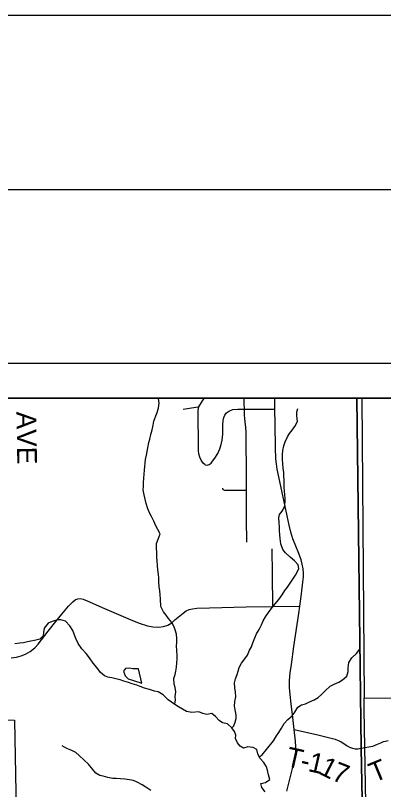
# Model space of a CAD drawing. Extents: x 0 to 34, y 0 to 22.
# Drawn here: x 5.25 to 6.308, y 19.775 to 22 of the extents above; entities that cross this region are included whole.
import ezdxf

# ---------------------------------------------------------------- set-up
doc = ezdxf.new("R2010")
doc.units = 0
for name, color, linetype in [('Default', 7, 'Continuous'), ('SH_Border', 7, 'Continuous'), ('SH_Cut_Line', 7, 'Continuous'), ('SH_Data', 7, 'Continuous')]:
    doc.layers.add(name, color=color, linetype=linetype)

msp = doc.modelspace()

# ---------------------------------------------------------------- linework, layer by layer
at = {"layer": 'Default'}
for points in [[(6.2766, 18.3021), (6.2705, 18.5012), (6.2432, 19.8937), (6.2315, 20.9), (2.1, 20.9)], [(5.7078, 20.0197), (5.7099, 20.0328), (5.709, 20.0422), (5.7106, 20.0559), (5.7089, 20.0677), (5.7056, 20.0775), (5.7049, 20.0935), (5.7085, 20.1057), (5.711, 20.1152), (5.7131, 20.1259), (5.714, 20.1388), (5.7145, 20.1499), (5.7143, 20.1594), (5.7136, 20.1742), (5.713, 20.1875), (5.714, 20.197), (5.7141, 20.2088), (5.7127, 20.2213), (5.7091, 20.2341), (5.7051, 20.2447), (5.6992, 20.2548), (5.6894, 20.2664), (5.6828, 20.2762), (5.675, 20.2859), (5.6678, 20.301), (5.6666, 20.323), (5.6653, 20.3344), (5.6643, 20.3472), (5.6633, 20.3567), (5.6623, 20.3723), (5.6617, 20.3833), (5.6607, 20.3928), (5.6593, 20.4061), (5.658, 20.4186), (5.6569, 20.4322), (5.6563, 20.4429), (5.6556, 20.4816), (5.6603, 20.4946), (5.6657, 20.5099), (5.659, 20.5223), (5.6535, 20.5329), (5.6479, 20.5464), (5.6404, 20.5596), (5.6349, 20.5701), (5.6305, 20.5818), (5.6256, 20.5969), (5.6223, 20.6098), (5.6194, 20.6222), (5.6172, 20.6359), (5.6174, 20.6458), (5.6176, 20.6564), (5.6185, 20.6693), (5.6198, 20.6815), (5.6211, 20.6926), (5.622, 20.7029), (5.6226, 20.7124), (5.6239, 20.7234), (5.626, 20.7356), (5.628, 20.7463), (5.6301, 20.7574), (5.6336, 20.7719), (5.6365, 20.7818), (5.6393, 20.7955), (5.6424, 20.8089), (5.6452, 20.8222), (5.6477, 20.8337), (5.6535, 20.8486), (5.6571, 20.8582), (5.6614, 20.872), (5.6626, 20.8853), (5.6609, 20.8986), (5.66, 20.9)], [(5.7765, 20.8745), (5.7871, 20.892), (5.7932, 20.9)], [(5.9148, 20.4853), (5.9135, 20.5521), (5.9139, 20.6343), (5.9135, 20.6961), (5.9132, 20.7724), (5.9125, 20.8022), (5.9117, 20.8165), (5.9102, 20.8305), (5.9078, 20.8516), (5.9078, 20.8677), (5.907, 20.8853), (5.9071, 20.9)], [(6.0294, 19.7703), (6.043, 19.8235), (6.0507, 19.8542), (6.054, 19.8702), (6.0556, 19.8831), (6.0558, 19.8974), (6.0547, 19.9136), (6.0509, 19.9471), (6.0469, 19.9819), (6.0423, 20.0205), (6.0395, 20.0481), (6.0379, 20.0678), (6.0379, 20.0885), (6.0396, 20.1096), (6.0429, 20.1342), (6.0503, 20.1859), (6.0643, 20.2808), (6.0674, 20.3022), (6.071, 20.3296), (6.076, 20.3703), (6.0775, 20.3858), (6.0776, 20.3968), (6.0768, 20.4092), (6.0744, 20.4225), (6.0708, 20.4354), (6.0645, 20.4529), (6.0554, 20.4745), (6.0472, 20.4956), (6.0415, 20.5146), (6.0368, 20.5342), (6.031, 20.5616), (6.0128, 20.6469), (6.0025, 20.6954), (5.9999, 20.7106), (5.9982, 20.7256), (5.997, 20.7568), (5.9963, 20.8247), (5.9958, 20.8681), (5.9956, 20.8961), (5.9956, 20.9)], [(8.9, 20.9), (6.2315, 20.9), (6.2432, 19.8937), (6.2705, 18.5012), (6.2766, 18.3021), (6.2818, 17.7893), (6.284, 17.7847), (6.2852, 17.7812), (6.2857, 17.7766), (6.2851, 17.77), (6.2847, 17.7673), (6.2837, 17.7609), (6.2829, 17.749), (6.2828, 17.7387), (6.2833, 17.73), (6.2837, 17.7277), (6.2841, 17.7253), (6.2843, 17.721), (6.2843, 17.7119), (6.2861, 17.2714), (6.2871, 17.0188), (6.3215, 17.0189)], [(5.7317, 20.8678), (5.7678, 20.8734), (5.7765, 20.8745)], [(5.7953, 20.7084), (5.7897, 20.7131), (5.784, 20.7212), (5.7801, 20.7298), (5.7773, 20.7394), (5.7762, 20.7495), (5.7758, 20.7573), (5.7755, 20.791), (5.775, 20.8268), (5.7751, 20.8501), (5.7751, 20.8641), (5.7765, 20.8745)], [(5.7953, 20.7084), (5.8007, 20.7072), (5.807, 20.7092), (5.8122, 20.7133), (5.8166, 20.7186), (5.8231, 20.7273), (5.8314, 20.7405), (5.8372, 20.7537), (5.8414, 20.7669), (5.8442, 20.7794), (5.8456, 20.7961), (5.846, 20.8233), (5.8467, 20.8352), (5.8488, 20.8441), (5.852, 20.8509), (5.8569, 20.8577), (5.8646, 20.8632), (5.8748, 20.8667), (5.8887, 20.8678), (5.9078, 20.8677), (5.9536, 20.8678), (5.9958, 20.8681)], [(5.8715, 19.9519), (5.8776, 19.9581), (5.8812, 19.9681), (5.8841, 19.9792), (5.8842, 19.9887), (5.8825, 19.9989), (5.8792, 20.0144), (5.8805, 20.0273), (5.8829, 20.0407), (5.8826, 20.0544), (5.8801, 20.0672), (5.879, 20.0813), (5.8819, 20.0927), (5.8869, 20.1057), (5.8898, 20.1153), (5.893, 20.1256), (5.9, 20.1379), (5.9093, 20.1499), (5.9167, 20.161), (5.9229, 20.1748), (5.928, 20.1844), (5.9324, 20.1967), (5.9382, 20.2105), (5.9429, 20.2224), (5.9499, 20.2343), (5.9569, 20.2477), (5.962, 20.2596), (5.9686, 20.2707), (5.9767, 20.2834), (5.9875, 20.2981), (5.996, 20.3085), (6.0064, 20.3212), (6.0161, 20.334), (6.0246, 20.3467), (6.032, 20.3567), (6.039, 20.3679), (6.0471, 20.3798), (6.0545, 20.391), (6.0601, 20.401), (6.0641, 20.4105), (6.062, 20.4204), (6.0518, 20.432), (6.0398, 20.4427), (6.0263, 20.455), (6.0181, 20.4651), (6.0128, 20.4813), (6.011, 20.4961), (6.0101, 20.5064), (6.0091, 20.5181), (6.0085, 20.5295), (6.0075, 20.5409), (6.0065, 20.5557), (6.0086, 20.5652), (6.0167, 20.5749), (6.023, 20.586), (6.0254, 20.6013), (6.0252, 20.6119), (6.0242, 20.6214), (6.0228, 20.6335), (6.0223, 20.643), (6.0221, 20.6537), (6.0223, 20.6639), (6.0216, 20.6761), (6.0211, 20.6856), (6.0193, 20.6988), (6.0187, 20.7114), (6.0173, 20.7246), (6.017, 20.7379), (6.0183, 20.7494), (6.0211, 20.7627), (6.0247, 20.7738), (6.0317, 20.7884), (6.0379, 20.7984), (6.045, 20.808), (6.0546, 20.8211), (6.0601, 20.8341), (6.0583, 20.8482), (6.0588, 20.8607), (6.0616, 20.8703)], [(5.9139, 20.6343), (5.8515, 20.6339), (5.8473, 20.6364), (5.8455, 20.6409)], [(5.9895, 20.3009), (5.9882, 20.3934), (5.9873, 20.467)], [(5.2378, 20.1528), (5.2524, 20.1548), (5.2659, 20.1586), (5.2786, 20.1637), (5.2919, 20.171), (5.3055, 20.1818), (5.3152, 20.1928), (5.3439, 20.2295), (5.3657, 20.2572), (5.3834, 20.279), (5.4021, 20.3014), (5.4144, 20.3141), (5.4226, 20.3205), (5.4292, 20.3232), (5.4359, 20.3239), (5.4439, 20.322), (5.4556, 20.317), (5.5056, 20.2948), (5.5797, 20.2633), (5.6054, 20.2528), (5.6291, 20.2456), (5.6444, 20.2421), (5.6607, 20.2413), (5.6749, 20.2428), (5.6877, 20.247), (5.6988, 20.2538), (5.7082, 20.2621), (5.7315, 20.2819), (5.7404, 20.2881), (5.7489, 20.2922), (5.759, 20.2945), (5.7713, 20.2957), (5.8078, 20.2968), (5.9133, 20.2994), (5.9895, 20.3009), (6.0674, 20.3022)], [(5.9676, 19.7676), (5.9583, 19.7803), (5.9554, 19.7917), (5.9683, 19.7946), (5.9807, 19.8032), (5.977, 19.8168), (5.9741, 19.8301), (5.9712, 19.8399), (5.9637, 19.8523), (5.9525, 19.865), (5.9461, 19.877), (5.9436, 19.8895), (5.9328, 19.8954), (5.918, 19.8977), (5.9055, 19.8937), (5.8959, 19.8988), (5.8885, 19.9086), (5.8821, 19.9214), (5.8831, 19.9313), (5.8798, 19.9411), (5.8713, 19.9523), (5.8589, 19.9635), (5.8451, 19.9666), (5.8351, 19.9733), (5.8246, 19.9848), (5.8138, 19.993), (5.8001, 19.9901), (5.7883, 19.9929), (5.7768, 19.998), (5.7563, 19.996), (5.7414, 19.9988), (5.7298, 20.0058), (5.7183, 20.012), (5.7083, 20.0194), (5.6983, 20.0253), (5.6886, 20.0327), (5.6739, 20.0465), (5.66, 20.0553), (5.6497, 20.0578), (5.6352, 20.0617), (5.621, 20.0656), (5.6084, 20.0703), (5.5984, 20.0743), (5.585, 20.0786), (5.5743, 20.0822), (5.5613, 20.0865), (5.5505, 20.0897), (5.5379, 20.0929), (5.5272, 20.0953), (5.515, 20.0973), (5.5054, 20.1017), (5.4946, 20.111), (5.4837, 20.1256), (5.4731, 20.1383), (5.463, 20.1529), (5.4528, 20.166), (5.4408, 20.1795), (5.4298, 20.1945), (5.4231, 20.2084), (5.4183, 20.2209), (5.4146, 20.2314), (5.406, 20.2453), (5.3932, 20.2587), (5.3802, 20.2627), (5.3703, 20.2625), (5.3548, 20.2576), (5.3442, 20.2528), (5.3319, 20.2389), (5.3299, 20.226), (5.3293, 20.2165), (5.3196, 20.2068), (5.3045, 20.2031), (5.2943, 20.201), (5.2844, 20.1992), (5.273, 20.1967), (5.2624, 20.195), (5.2484, 20.1932)], [(5.9505, 19.8687), (5.9591, 19.8746), (5.971, 19.89), (5.9918, 19.9148), (6.0003, 19.9286), (6.0073, 19.9382), (6.0143, 19.9509), (6.0224, 19.9644), (6.0329, 19.9756), (6.0456, 19.9869), (6.0526, 19.9969), (6.0611, 20.0111), (6.0724, 20.0178), (6.0834, 20.021), (6.0935, 20.0254), (6.1083, 20.0322), (6.1203, 20.0392), (6.13, 20.0478), (6.1401, 20.0582), (6.1543, 20.0714), (6.1664, 20.077), (6.1792, 20.0837), (6.1901, 20.09), (6.2028, 20.1005), (6.206, 20.1139), (6.2058, 20.1249), (6.2081, 20.1401), (6.2166, 20.1532), (6.2297, 20.1653), (6.2397, 20.178)], [(5.6036, 20.1211), (5.5872, 20.1219), (5.5765, 20.1232), (5.5663, 20.1227), (5.5607, 20.1153), (5.5651, 20.1017), (5.5741, 20.0928), (5.5886, 20.0878), (5.6127, 20.0806)], [(5.6127, 20.0806), (5.6036, 20.1211)], [(6.0509, 19.9471), (6.1186, 19.9316), (6.1692, 19.9189), (6.1778, 19.9158), (6.1852, 19.9122), (6.2038, 19.9003), (6.2105, 19.8964), (6.219, 19.8933), (6.226, 19.892), (6.2342, 19.892), (6.2434, 19.8932)], [(5.6392, 19.7718), (5.6246, 19.7818), (5.6142, 19.7881), (5.5996, 19.7962), (5.5888, 19.8005), (5.5778, 19.8022), (5.564, 19.8042), (5.5519, 19.8051), (5.5393, 19.8064), (5.5298, 19.8066), (5.5156, 19.809), (5.5022, 19.8132), (5.4927, 19.8153), (5.4808, 19.8219), (5.4726, 19.832), (5.4597, 19.847), (5.4473, 19.8593), (5.433, 19.8727), (5.4229, 19.8809), (5.4118, 19.8871), (5.3976, 19.8925), (5.3841, 19.9002)], [(6.2434, 19.8932), (6.2772, 19.8988), (6.2903, 19.9047), (6.2999, 19.9091), (6.3082, 19.9123), (6.3131, 19.9138), (6.3212, 19.9159)]]:
    msp.add_lwpolyline(points, dxfattribs=at)
for points in [[(7.1051, 20.9), (6.2451, 20.9), (6.2523, 20.0379), (7.1182, 20.0358)], [(6.2523, 20.0379), (7.1182, 20.0358), (7.1411, 19.0266), (6.2698, 19.0329), (6.2526, 20.0047)], [(4.2696, 19.9768), (5.2472, 19.9737), (5.2648, 18.9869), (4.2649, 18.9814)]]:
    msp.add_lwpolyline(points, close=True, dxfattribs=at)
at = {"layer": 'SH_Border'}
msp.add_lwpolyline([(1.5, 21.5), (33.5, 21.5), (33.5, 0.5), (1.5, 0.5)], close=True, dxfattribs=at)
at = {"layer": 'SH_Cut_Line'}
msp.add_lwpolyline([(0, 0), (34, 0), (34, 22), (0, 22)], close=True, dxfattribs=at)
for points in [[(6.2766, 18.3021), (6.2705, 18.5012), (6.2432, 19.8937), (6.2315, 20.9), (2.1, 20.9)], [(8.9, 20.9), (6.2315, 20.9), (6.2432, 19.8937), (6.2705, 18.5012), (6.2766, 18.3021), (6.2818, 17.7893), (6.284, 17.7847), (6.2852, 17.7812), (6.2857, 17.7766), (6.2851, 17.77), (6.2847, 17.7673), (6.2837, 17.7609), (6.2829, 17.749), (6.2828, 17.7387), (6.2833, 17.73), (6.2837, 17.7277), (6.2841, 17.7253), (6.2843, 17.721), (6.2843, 17.7119), (6.2861, 17.2714), (6.2871, 17.0188), (6.3215, 17.0189)]]:
    msp.add_lwpolyline(points, dxfattribs=at)
at = {"layer": 'SH_Data'}
for p, q in [((2, 21), (9, 21)), ((2.1, 20.9), (8.9, 20.9))]:
    msp.add_line(p, q, dxfattribs=at)

# ---------------------------------------------------------------- texts
at = {"layer": 'Default'}
for s, height, rotation, p in [('AVE', 0.05682, 271.0032, (5.2524, 20.8609)), ('T', 0.0568, 347.2527, (6.0241, 19.8425)), ('1', 0.0568, 347.2618, (6.0883, 19.828)), ('-', 0.0568, 347.2476, (6.0655, 19.8331)), ('1', 0.0568, 332.9834, (6.1189, 19.8215)), ('7', 0.0568, 338.6304, (6.1557, 19.8031)), ('T', 0.0568, 22.485, (6.2807, 19.7937))]:
    msp.add_text(s, height=height, rotation=rotation, dxfattribs=at).set_placement(p)

doc.saveas('drawing.dxf')
